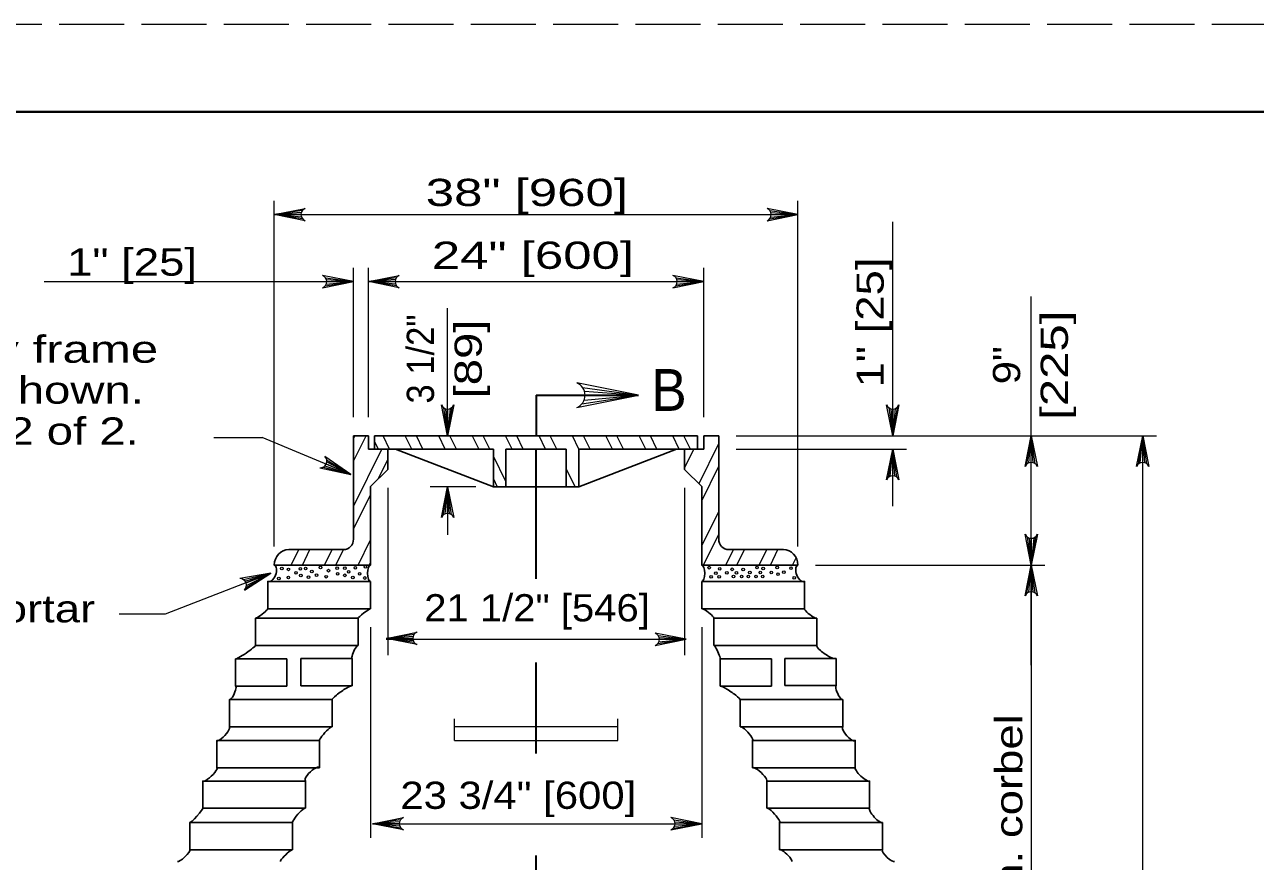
# Model space of a CAD drawing. Extents: x 1083.1 to 1117.1, y 697.4 to 741.4.
# Drawn here: x 1087.29 to 1094.35, y 736.56 to 741.35 of the extents above; entities that cross this region are included whole.
import ezdxf
from ezdxf.enums import TextEntityAlignment as Align

# ---------------------------------------------------------------- set-up
doc = ezdxf.new("R2010")
doc.units = 0
doc.header["$LTSCALE"] = 0.062
doc.linetypes.add('LONG_DASHED', pattern=[7.5, 6, -1.5])
doc.layers.add('1', color=7, linetype='Continuous', lineweight=13)

msp = doc.modelspace()

# ---------------------------------------------------------------- linework, layer by layer
at = {"layer": '1', "lineweight": 25}
for p, q in [((1085.12642, 740.85408), (1116.62642, 740.85408)), ((1089.17683, 738.40442), (1089.17683, 738.99733)), ((1089.17683, 738.99733), (1089.26217, 738.99733)), ((1089.26217, 738.92125), (1089.26217, 738.99733)), ((1089.29817, 738.92125), (1089.29817, 738.99733)), ((1089.29817, 738.99733), (1091.14983, 738.99733)), ((1091.14983, 738.92125), (1091.14983, 738.99733)), ((1091.18575, 738.92125), (1091.18575, 738.99733)), ((1091.27108, 738.99733), (1091.18575, 738.99733)), ((1091.27108, 738.40442), (1091.27108, 738.99733)), ((1089.26217, 738.92125), (1089.979, 738.92125)), ((1089.37358, 738.8045), (1089.37358, 738.92125)), ((1089.979, 738.70492), (1089.41875, 738.92125)), ((1089.979, 738.70492), (1089.979, 738.92125)), ((1090.05092, 738.70442), (1090.05083, 738.92125)), ((1090.05083, 738.92125), (1090.39708, 738.92125)), ((1090.39708, 738.70442), (1090.39708, 738.92125)), ((1090.469, 738.70492), (1090.46892, 738.92125)), ((1090.46892, 738.92125), (1091.18575, 738.92125)), ((1090.469, 738.70492), (1091.02917, 738.92125)), ((1091.07433, 738.8045), (1091.07433, 738.92125)), ((1089.27425, 738.70733), (1089.37358, 738.8045)), ((1091.17375, 738.70733), (1091.07433, 738.8045)), ((1089.979, 738.70492), (1090.05092, 738.70442)), ((1090.39708, 738.70442), (1090.05092, 738.70442)), ((1090.469, 738.70492), (1090.39708, 738.70442)), ((1088.80608, 738.34442), (1089.12025, 738.34442)), ((1091.64192, 738.34442), (1091.32775, 738.34442)), ((1089.27425, 738.00592), (1089.27425, 738.16192)), ((1091.17375, 738.00592), (1091.17375, 738.16192)), ((1088.685, 738.00592), (1089.27425, 738.00592)), ((1091.763, 738.00592), (1091.17375, 738.00592)), ((1089.20425, 737.79567), (1089.20425, 737.95158)), ((1091.24375, 737.79567), (1091.24375, 737.95158)), ((1088.615, 737.79567), (1089.20425, 737.79567)), ((1091.83292, 737.79567), (1091.24375, 737.79567)), ((1088.79558, 737.71808), (1088.50092, 737.71808)), ((1088.50092, 737.56217), (1088.50092, 737.71808)), ((1088.79558, 737.56217), (1088.79558, 737.71808)), ((1089.16958, 737.72033), (1088.875, 737.72033)), ((1088.875, 737.56442), (1088.875, 737.72033)), ((1089.16958, 737.56442), (1089.16958, 737.72033)), ((1091.57383, 737.71825), (1091.27925, 737.71825)), ((1091.27925, 737.56233), (1091.27925, 737.71825)), ((1091.57383, 737.56233), (1091.57383, 737.71825)), ((1091.94467, 737.72083), (1091.65, 737.72083)), ((1091.65, 737.56483), (1091.65, 737.72083)), ((1091.94467, 737.56483), (1091.94467, 737.72083)), ((1088.79558, 737.56217), (1088.50092, 737.56217)), ((1089.16958, 737.56442), (1088.875, 737.56442)), ((1091.57383, 737.56233), (1091.27925, 737.56233)), ((1091.94467, 737.56492), (1091.65, 737.56492)), ((1089.05475, 737.329), (1089.05475, 737.48492)), ((1091.39317, 737.329), (1091.39317, 737.48492)), ((1088.46558, 737.329), (1089.05475, 737.329)), ((1091.98242, 737.329), (1091.39317, 737.329)), ((1088.98292, 737.09467), (1088.98292, 737.25058)), ((1091.46508, 737.09467), (1091.46508, 737.25058)), ((1088.39367, 737.09467), (1088.98292, 737.09467)), ((1092.05433, 737.09467), (1091.46508, 737.09467)), ((1088.9015, 736.86233), (1088.9015, 737.01825)), ((1091.54642, 736.86233), (1091.54642, 737.01825)), ((1088.31233, 736.86233), (1088.9015, 736.86233)), ((1092.13567, 736.86233), (1091.54642, 736.86233)), ((1088.82775, 736.62392), (1088.82775, 736.77992)), ((1091.62017, 736.62392), (1091.62017, 736.77992)), ((1088.2385, 736.62392), (1088.82775, 736.62392)), ((1092.20942, 736.62392), (1091.62017, 736.62392))]:
    msp.add_line(p, q, dxfattribs=at)
at = {"layer": '1'}
for p, q in [((1088.72283, 738.36233), (1088.72283, 740.344)), ((1091.72517, 738.36233), (1091.72517, 740.344)), ((1088.88308, 740.28775), (1088.72283, 740.26533)), ((1088.87767, 740.27667), (1088.72283, 740.26533)), ((1088.72283, 740.26533), (1090.54142, 740.26533)), ((1088.876, 740.26533), (1088.72283, 740.26533)), ((1088.87883, 740.25092), (1088.72283, 740.26533)), ((1088.88492, 740.24058), (1088.72283, 740.26533)), ((1090.54142, 740.26533), (1091.72517, 740.26533)), ((1091.563, 740.24058), (1091.72517, 740.26533)), ((1091.56492, 740.28775), (1091.72517, 740.26533)), ((1091.56917, 740.25092), (1091.72517, 740.26533)), ((1091.57033, 740.27667), (1091.72517, 740.26533)), ((1091.572, 740.26533), (1091.72517, 740.26533)), ((1092.26917, 738.99733), (1092.26917, 740.22292)), ((1089.01658, 739.90325), (1089.17683, 739.88083)), ((1089.17683, 739.10342), (1089.17683, 739.9595)), ((1089.26217, 739.10342), (1089.26217, 739.9595)), ((1089.42242, 739.90325), (1089.26217, 739.88083)), ((1091.0255, 739.90325), (1091.18575, 739.88083)), ((1091.18575, 739.10342), (1091.18575, 739.9595)), ((1087.40358, 739.88083), (1089.17683, 739.88083)), ((1089.01475, 739.856), (1089.17683, 739.88083)), ((1089.02083, 739.86642), (1089.17683, 739.88083)), ((1089.02208, 739.89217), (1089.17683, 739.88083)), ((1089.02367, 739.88083), (1089.17683, 739.88083)), ((1089.417, 739.89217), (1089.26217, 739.88083)), ((1089.41533, 739.88083), (1089.26217, 739.88083)), ((1089.41817, 739.86642), (1089.26217, 739.88083)), ((1089.42433, 739.856), (1089.26217, 739.88083)), ((1089.26217, 739.88083), (1091.18575, 739.88083)), ((1091.02358, 739.856), (1091.18575, 739.88083)), ((1091.02975, 739.86642), (1091.18575, 739.88083)), ((1091.03092, 739.89217), (1091.18575, 739.88083)), ((1091.03258, 739.88083), (1091.18575, 739.88083)), ((1093.06292, 738.25633), (1093.06292, 739.79558)), ((1089.71608, 738.99733), (1089.71608, 739.72883)), ((1090.49083, 739.27442), (1090.81125, 739.22958)), ((1090.487, 739.18), (1090.81125, 739.22958)), ((1090.49933, 739.20075), (1090.81125, 739.22958)), ((1090.50167, 739.25225), (1090.81125, 739.22958)), ((1090.505, 739.22958), (1090.81125, 739.22958)), ((1089.69367, 739.15758), (1089.71608, 738.99733)), ((1089.70475, 739.15217), (1089.71608, 738.99733)), ((1089.74092, 739.1595), (1089.71608, 738.99733)), ((1089.7305, 739.15333), (1089.71608, 738.99733)), ((1089.71608, 739.1505), (1089.71608, 738.99733)), ((1092.24675, 739.15758), (1092.26917, 738.99733)), ((1092.25783, 739.15217), (1092.26917, 738.99733)), ((1092.29392, 739.1595), (1092.26917, 738.99733)), ((1092.2835, 739.15333), (1092.26917, 738.99733)), ((1092.26917, 739.1505), (1092.26917, 738.99733)), ((1088.3755, 738.9875), (1088.653, 738.9875)), ((1089.16083, 738.775), (1088.653, 738.9875)), ((1089.17683, 738.85092), (1089.249, 738.99733)), ((1089.17683, 738.98058), (1089.18517, 738.99733)), ((1089.38375, 738.92125), (1089.34625, 738.99733)), ((1089.39833, 738.99733), (1089.81625, 738.99733)), ((1089.5115, 738.92125), (1089.474, 738.99733)), ((1089.57542, 738.92125), (1089.53792, 738.99733)), ((1089.70317, 738.92125), (1089.66567, 738.99733)), ((1089.76708, 738.92125), (1089.72958, 738.99733)), ((1089.85733, 738.99733), (1089.89483, 738.92125)), ((1089.95875, 738.92125), (1089.92125, 738.99733)), ((1090.0865, 738.92125), (1090.049, 738.99733)), ((1090.15042, 738.92125), (1090.11292, 738.99733)), ((1090.27817, 738.92125), (1090.24067, 738.99733)), ((1090.34208, 738.92125), (1090.3045, 738.99733)), ((1090.46983, 738.92125), (1090.43233, 738.99733)), ((1090.53367, 738.92125), (1090.49617, 738.99733)), ((1090.6615, 738.92125), (1090.624, 738.99733)), ((1090.72533, 738.92125), (1090.68783, 738.99733)), ((1090.85317, 738.92125), (1090.81558, 738.99733)), ((1090.917, 738.92125), (1090.8795, 738.99733)), ((1091.04475, 738.92125), (1091.00725, 738.99733)), ((1091.10867, 738.92125), (1091.07117, 738.99733)), ((1091.37125, 738.99733), (1093.78125, 738.99733)), ((1091.37125, 738.99733), (1092.36925, 738.99733)), ((1091.47142, 738.99733), (1093.064, 738.99733)), ((1093.03817, 738.83525), (1093.06292, 738.99733)), ((1093.0485, 738.84133), (1093.06292, 738.99733)), ((1093.06292, 738.84417), (1093.06292, 738.99733)), ((1093.07425, 738.84258), (1093.06292, 738.99733)), ((1093.08533, 738.83708), (1093.06292, 738.99733)), ((1093.67775, 738.83525), (1093.70258, 738.99733)), ((1093.68817, 738.84133), (1093.70258, 738.99733)), ((1093.70258, 733.89467), (1093.70258, 738.99733)), ((1093.70258, 738.84417), (1093.70258, 738.99733)), ((1093.71392, 738.84258), (1093.70258, 738.99733)), ((1093.725, 738.83708), (1093.70258, 738.99733)), ((1089.17683, 738.59167), (1089.33925, 738.92125)), ((1089.31992, 738.92125), (1089.29817, 738.96533)), ((1091.07433, 738.81225), (1091.12808, 738.92125)), ((1091.158, 738.72275), (1091.27108, 738.95217)), ((1091.37125, 738.92125), (1092.34783, 738.92125)), ((1092.24433, 738.75908), (1092.26917, 738.92125)), ((1092.25475, 738.76525), (1092.26917, 738.92125)), ((1092.26917, 738.59308), (1092.26917, 738.92125)), ((1092.26917, 738.76808), (1092.26917, 738.92125)), ((1092.2805, 738.76642), (1092.26917, 738.92125)), ((1092.29158, 738.761), (1092.26917, 738.92125)), ((1089.02317, 738.86), (1089.16083, 738.775)), ((1089.02367, 738.84767), (1089.16083, 738.775)), ((1089.31958, 738.75167), (1089.37358, 738.86125)), ((1090.05092, 738.73425), (1089.979, 738.88017)), ((1089.00242, 738.81758), (1089.16083, 738.775)), ((1089.01225, 738.82458), (1089.16083, 738.775)), ((1089.02058, 738.83667), (1089.16083, 738.775)), ((1090.44875, 738.70483), (1090.39708, 738.80958)), ((1091.17375, 738.625), (1091.27108, 738.82258)), ((1089.37358, 738.69842), (1089.37358, 737.74058)), ((1089.87883, 738.70492), (1089.61592, 738.70492)), ((1089.69133, 738.54283), (1089.71608, 738.70492)), ((1089.70175, 738.54892), (1089.71608, 738.70492)), ((1089.71608, 738.70492), (1089.71608, 738.42975)), ((1089.71608, 738.55175), (1089.71608, 738.70492)), ((1089.72742, 738.55008), (1089.71608, 738.70492)), ((1089.7385, 738.54467), (1089.71608, 738.70492)), ((1089.979, 738.7505), (1090.0015, 738.70475)), ((1091.07433, 738.69842), (1091.07433, 737.74058)), ((1089.17683, 738.462), (1089.27425, 738.65958)), ((1091.17375, 738.36567), (1091.27108, 738.56325)), ((1091.18367, 738.25633), (1091.27108, 738.43367)), ((1093.0405, 738.41658), (1093.06292, 738.25633)), ((1093.08775, 738.41842), (1093.06292, 738.25633)), ((1088.81992, 738.25633), (1088.86333, 738.34442)), ((1088.88383, 738.25633), (1088.92725, 738.34442)), ((1089.01158, 738.25633), (1089.055, 738.34442)), ((1089.0755, 738.25633), (1089.11892, 738.34442)), ((1089.20325, 738.25633), (1089.27425, 738.40033)), ((1091.3115, 738.25633), (1091.35492, 738.34442)), ((1091.37533, 738.25633), (1091.41875, 738.34442)), ((1091.50308, 738.25633), (1091.54658, 738.34442)), ((1091.567, 738.25633), (1091.61042, 738.34442)), ((1093.05158, 738.41108), (1093.06292, 738.25633)), ((1093.07733, 738.41233), (1093.06292, 738.25633)), ((1093.06292, 738.4095), (1093.06292, 738.25633)), ((1091.69475, 738.25633), (1091.71525, 738.29792)), ((1088.54625, 738.17258), (1088.70392, 738.20908)), ((1088.55533, 738.16417), (1088.70392, 738.20908)), ((1088.56092, 738.15417), (1088.70392, 738.20908)), ((1088.56142, 738.12783), (1088.70392, 738.20908)), ((1088.56342, 738.13975), (1088.70392, 738.20908)), ((1089.26717, 738.25633), (1089.27425, 738.27067)), ((1091.82525, 738.25633), (1093.14158, 738.25633)), ((1093.03817, 738.09417), (1093.06292, 738.25633)), ((1093.0485, 738.10033), (1093.06292, 738.25633)), ((1093.06292, 738.25633), (1093.06292, 735.13425)), ((1093.06292, 737.68233), (1093.06292, 738.25633)), ((1093.06292, 738.10317), (1093.06292, 738.25633)), ((1093.07425, 738.1015), (1093.06292, 738.25633)), ((1093.08533, 738.09608), (1093.06292, 738.25633)), ((1089.27425, 737.89992), (1089.27425, 736.692)), ((1089.52442, 737.8585), (1089.36417, 737.83608)), ((1090.92358, 737.85292), (1091.08383, 737.8305)), ((1091.17375, 737.89992), (1091.17375, 736.692)), ((1089.519, 737.84742), (1089.36417, 737.83608)), ((1089.51733, 737.83608), (1089.36417, 737.83608)), ((1089.52017, 737.82167), (1089.36417, 737.83608)), ((1089.52625, 737.81133), (1089.36417, 737.83608)), ((1089.36417, 737.8305), (1091.07433, 737.8305)), ((1090.92167, 737.80567), (1091.08383, 737.8305)), ((1090.92783, 737.81608), (1091.08383, 737.8305)), ((1090.929, 737.84183), (1091.08383, 737.8305)), ((1090.93067, 737.8305), (1091.08383, 737.8305)), ((1089.75575, 737.25), (1089.75575, 737.37533)), ((1090.69217, 737.25), (1090.69217, 737.37533)), ((1089.75575, 737.33133), (1090.69217, 737.33133)), ((1089.75575, 737.25), (1090.69217, 737.25)), ((1089.44642, 736.79592), (1089.28625, 736.77342)), ((1091.0135, 736.79592), (1091.17375, 736.77342)), ((1089.441, 736.78475), (1089.28625, 736.77342)), ((1089.43942, 736.77342), (1089.28625, 736.77342)), ((1089.44225, 736.75908), (1089.28625, 736.77342)), ((1089.44833, 736.74867), (1089.28625, 736.77342)), ((1089.28625, 736.77342), (1091.17375, 736.77342)), ((1091.01158, 736.74867), (1091.17375, 736.77342)), ((1091.01775, 736.75908), (1091.17375, 736.77342)), ((1091.01892, 736.78475), (1091.17375, 736.77342)), ((1091.02058, 736.77342), (1091.17375, 736.77342))]:
    msp.add_line(p, q, dxfattribs=at)
at = {"layer": '1', "lineweight": 35}
for p, q in [((1090.224, 739.22958), (1090.81125, 739.22958)), ((1090.224, 739.22958), (1090.224, 738.99733)), ((1090.224, 738.17692), (1090.224, 738.92125)), ((1090.224, 737.1755), (1090.224, 737.69717)), ((1090.224, 730.90125), (1090.224, 736.59083))]:
    msp.add_line(p, q, dxfattribs=at)
at = {"layer": '1', "linetype": 'LONG_DASHED'}
msp.add_lwpolyline([(1083.12642, 719.35408), (1117.12642, 719.35408), (1117.12642, 741.35408), (1083.12642, 741.35408)], close=True, dxfattribs=at)
at = {"layer": '1', "lineweight": 40}
msp.add_lwpolyline([(1085.12642, 740.85408), (1116.62642, 740.85408), (1116.62642, 719.85408), (1085.12642, 719.85408)], close=True, dxfattribs=at)
at = {"layer": '1'}
for points in [[(1088.89983, 740.22992), (1088.72283, 740.26533), (1088.89983, 740.30075)], [(1091.54817, 740.22992), (1091.72517, 740.26533), (1091.54817, 740.30075)], [(1088.99983, 739.84542), (1089.17683, 739.88083), (1088.99983, 739.91625)], [(1089.43917, 739.84542), (1089.26217, 739.88083), (1089.43917, 739.91625)], [(1091.00875, 739.84542), (1091.18575, 739.88083), (1091.00875, 739.91625)], [(1089.26217, 739.88083), (1090.52358, 739.88083), (1091.18575, 739.88083)], [(1090.45725, 739.15875), (1090.81125, 739.22958), (1090.45725, 739.30033)], [(1089.7515, 739.17433), (1089.71608, 738.99733), (1089.68067, 739.17433)], [(1092.3045, 739.17433), (1092.26917, 738.99733), (1092.23375, 739.17433)], [(1093.0275, 738.82033), (1093.06292, 738.99733), (1093.09833, 738.82033)], [(1093.66717, 738.82033), (1093.70258, 738.99733), (1093.738, 738.82033)], [(1092.23375, 738.74425), (1092.26917, 738.92125), (1092.3045, 738.74425)], [(1088.9845, 738.81383), (1089.16083, 738.775), (1089.01308, 738.87867)], [(1089.68067, 738.52792), (1089.71608, 738.70492), (1089.7515, 738.52792)], [(1093.09833, 738.43333), (1093.06292, 738.25633), (1093.0275, 738.43333)], [(1088.70392, 738.20908), (1088.09783, 737.97517), (1087.83292, 737.97517)], [(1088.55133, 738.11258), (1088.70392, 738.20908), (1088.526, 738.17875)], [(1093.0275, 738.07933), (1093.06292, 738.25633), (1093.09833, 738.07933)], [(1089.54117, 737.80067), (1089.36417, 737.83608), (1089.54117, 737.8715)], [(1090.90683, 737.79508), (1091.08383, 737.8305), (1090.90683, 737.86592)], [(1089.46325, 736.73808), (1089.28625, 736.77342), (1089.46325, 736.80883)], [(1090.99675, 736.73808), (1091.17375, 736.77342), (1090.99675, 736.80883)]]:
    msp.add_lwpolyline(points, dxfattribs=at)
at = {"layer": '1', "lineweight": 25}
for points in [[(1088.72283, 738.25633), (1089.27425, 738.25633), (1089.27425, 738.70733)], [(1091.72517, 738.25633), (1091.17375, 738.25633), (1091.17375, 738.70733)], [(1088.685, 738.00592), (1088.685, 738.16192), (1089.27425, 738.16192)], [(1091.763, 738.00592), (1091.763, 738.16192), (1091.17375, 738.16192)], [(1088.615, 737.79567), (1088.615, 737.95158), (1089.20425, 737.95158)], [(1091.83292, 737.79567), (1091.83292, 737.95158), (1091.24375, 737.95158)], [(1088.46558, 737.329), (1088.46558, 737.48492), (1089.05475, 737.48492)], [(1091.98242, 737.329), (1091.98242, 737.48492), (1091.39317, 737.48492)], [(1088.39367, 737.09467), (1088.39367, 737.25058), (1088.98292, 737.25058)], [(1092.05433, 737.09467), (1092.05433, 737.25058), (1091.46508, 737.25058)], [(1088.31233, 736.86233), (1088.31233, 737.01825), (1088.9015, 737.01825)], [(1092.13567, 736.86233), (1092.13567, 737.01825), (1091.54642, 737.01825)], [(1088.2385, 736.62392), (1088.2385, 736.77992), (1088.82775, 736.77992)], [(1092.20942, 736.62392), (1092.20942, 736.77992), (1091.62017, 736.77992)]]:
    msp.add_lwpolyline(points, dxfattribs=at)
at = {"layer": '1'}
for centre, radius, start, end in [((1088.91411, 740.26539), 0.0382, 112.08782, 247.91395), ((1091.53383, 740.26539), 0.0382, 292.08605, 67.91218), ((1088.98556, 739.88085), 0.0382, 292.08605, 67.91218), ((1089.4535, 739.88085), 0.0382, 112.08782, 247.91395), ((1090.99445, 739.88085), 0.0382, 292.08605, 67.91218), ((1090.4287, 739.22964), 0.0764, 292.08605, 67.91218), ((1089.71607, 739.18866), 0.0382, 202.08782, 337.91395), ((1092.26909, 739.18866), 0.0382, 202.08782, 337.91395), ((1088.98573, 738.85203), 0.0382, 268.33738, 44.16351), ((1093.06298, 738.80607), 0.0382, 22.08782, 157.91395), ((1093.7026, 738.80607), 0.0382, 22.08782, 157.91395), ((1092.26917, 738.72996), 0.0382, 22.08782, 157.91395), ((1089.71615, 738.51364), 0.0382, 22.08782, 157.91395), ((1093.0629, 738.44759), 0.0382, 202.08782, 337.91395), ((1088.52531, 738.14058), 0.0382, 313.08668, 88.9128), ((1093.06298, 738.065), 0.0382, 22.08782, 157.91395), ((1089.55545, 737.83614), 0.0382, 112.08782, 247.91395), ((1090.8925, 737.83052), 0.0382, 292.08605, 67.91218), ((1089.47751, 736.77349), 0.0382, 112.08782, 247.91395), ((1090.98243, 736.77349), 0.0382, 292.08605, 67.91218)]:
    msp.add_arc(centre, radius, start, end, dxfattribs=at)
at = {"layer": '1', "lineweight": 25}
for centre, major_axis, ratio, start_param, end_param in [((1088.80606, 738.2563), (0, 0.08813), 0.944544, 0.0000048, 1.5708011), ((1089.12022, 738.40439), (0, -0.05997), 0.944544, 0.000001, 1.5707952), ((1091.32773, 738.40439), (0, 0.05997), 0.944544, 1.5707952, 3.1415937), ((1091.64189, 738.2563), (0, 0.08813), 0.944544, 4.7123842, 6.2831805), ((1088.70391, 738.2091), (0.01807, 0.04755), 0.550574, 3.1091398, 6.2507324), ((1089.27423, 738.2091), (0, -0.0472), 0.356664, 3.1415929, 6.2831855), ((1091.17372, 738.2091), (0, -0.0472), 0.356664, 6.2831851, 9.4247777), ((1091.74404, 738.2091), (-0.01807, 0.04755), 0.550574, 0.0324529, 3.1740455), ((1088.64999, 737.97877), (0.03498, 0.0272), 0.123309, 3.1347753, 6.276368), ((1089.23923, 737.97877), (-0.03499, -0.02719), 0.095152, 3.1363648, 6.2779574), ((1091.20872, 737.97877), (0.03496, -0.02722), 0.153945, 0.0085851, 3.1501778), ((1091.79796, 737.97877), (-0.03495, 0.02724), 0.182617, 0.0102861, 3.1518788), ((1088.55797, 737.75688), (0.05701, 0.03878), 0.08505, 3.1371461, 6.2787387), ((1089.18691, 737.75799), (-0.01723, -0.03769), 0.223335, 3.131028, 6.2726207), ((1091.26147, 737.75696), (0.01773, -0.03869), 0.12471, 0.0056867, 3.1472794), ((1091.8888, 737.75823), (-0.05576, 0.03755), 0.215308, 0.0116463, 3.153239), ((1089.11219, 737.52466), (-0.05738, -0.03979), 0.123692, 3.1350238, 6.2766165), ((1088.48324, 737.52355), (0.01758, 0.03869), 0.261975, 3.1289792, 6.2705719), ((1091.3362, 737.52363), (0.05694, -0.03875), 0.114762, 0.0060354, 3.1476281), ((1091.96353, 737.5249), (-0.01874, 0.04005), 0.262161, 0.0128537, 3.1544464), ((1088.4296, 737.28978), (0.03579, 0.03934), 0.255117, 3.1260199, 6.2676126), ((1089.01883, 737.28978), (-0.03589, -0.03924), 0.153621, 3.1326147, 6.2742074), ((1091.42911, 737.28978), (0.03583, -0.0393), 0.2262, 0.0136046, 3.1551973), ((1092.01835, 737.28977), (-0.03567, 0.03945), 0.332158, 0.0213096, 3.1629023), ((1088.35298, 737.05644), (0.04053, 0.03834), 0.248819, 3.1265579, 6.2681506), ((1088.94222, 737.05644), (0.04038, 0.03851), 0.348106, 6.2607285, 9.4023212), ((1091.50573, 737.05644), (0.04056, -0.03832), 0.228756, 0.0136823, 3.155275), ((1092.09497, 737.05644), (-0.04055, 0.03833), 0.239953, 0.0144322, 3.1560248), ((1088.27542, 736.8211), (0.03686, 0.04122), 0.109562, 3.1352712, 6.2768638), ((1088.86465, 736.8211), (-0.03683, -0.04125), 0.157731, 3.1323715, 6.2739642), ((1091.5833, 736.8211), (0.03679, -0.04129), 0.204334, 0.0121564, 3.1537491), ((1092.17253, 736.8211), (-0.03675, 0.04132), 0.238818, 0.0144388, 3.1560314), ((1088.20353, 736.59077), (0.03491, 0.03328), 0.214158, 3.1288563, 6.2704489), ((1088.79276, 736.59077), (-0.03496, -0.03322), 0.136714, 3.1336877, 6.2752804), ((1091.65519, 736.59077), (0.0349, -0.03329), 0.223095, 0.0133225, 3.1549152), ((1092.24442, 736.59077), (-0.03485, 0.03334), 0.271388, 0.0166254, 3.158218)]:
    msp.add_ellipse(centre, major_axis=major_axis, ratio=ratio, start_param=start_param, end_param=end_param, dxfattribs=at)
at = {"layer": '1'}
for centre in [(1088.76618, 738.23586), (1088.8038, 738.23151), (1088.84754, 738.21089), (1088.87235, 738.23395), (1088.87487, 738.1962), (1088.90253, 738.23664), (1088.93806, 738.21899), (1088.96535, 738.19849), (1088.98755, 738.24188), (1089.03405, 738.22415), (1089.08348, 738.23833), (1089.08603, 738.20638), (1089.1271, 738.1974), (1089.12734, 738.23803), (1089.14915, 738.21757), (1089.18767, 738.24053), (1089.21214, 738.20553), (1089.24528, 738.24594), (1091.21646, 738.24136), (1091.25465, 738.20918), (1091.27674, 738.23515), (1091.31772, 738.21165), (1091.348, 738.23176), (1091.37255, 738.21128), (1091.41106, 738.23134), (1091.44933, 738.21367), (1091.49063, 738.24241), (1091.50964, 738.21326), (1091.52623, 738.23637), (1091.5727, 738.21284), (1091.60577, 738.24164), (1091.61103, 738.20387), (1091.644, 738.21526), (1091.68526, 738.2382), (1088.74865, 738.17963), (1088.80352, 738.18507), (1088.91868, 738.18719), (1089.02013, 738.18941), (1089.17363, 738.18547), (1089.24216, 738.18211), (1091.22711, 738.18904), (1091.27372, 738.18873), (1091.35598, 738.19108), (1091.40259, 738.19076), (1091.44097, 738.1905), (1091.48483, 738.19021), (1091.52321, 738.18995), (1091.70412, 738.18292)]:
    msp.add_ellipse(centre, major_axis=(0, 0.00779), ratio=0.944544, dxfattribs=at)

# ---------------------------------------------------------------- texts
for s, height, width, p in [('38" [960]', 0.156, 1.4, (1089.5915, 740.31417)), ('24" [600]', 0.156, 1.4, (1089.62625, 739.95417)), ('1" [25]', 0.156, 1.25, (1087.535, 739.915)), ('Heavy duty frame', 0.156, 1.35, (1085.85, 739.41583)), ('and cover shown.', 0.156, 1.3, (1085.85, 739.18117)), ('B', 0.24, 0.95, (1090.88417, 739.13983)), ('See Sheet 2 of 2.', 0.156, 1.3, (1085.85, 738.9465)), ('Mortar', 0.156, 1.25, (1086.94292, 737.92783)), ('23 3/4" [600]', 0.156, 1.15, (1089.44575, 736.85858))]:
    msp.add_text(s, height=height, dxfattribs=dict(at, width=width)).set_placement(p)
at = {"layer": '1', "width": 1.25}
for s, p in [('1" [25]', (1092.21708, 739.27408)), ('4\'-0" [1.2 m] min. corbel', (1093.01158, 734.66483))]:
    msp.add_text(s, height=0.156, rotation=90, dxfattribs=at).set_placement(p)
at = {"layer": '1'}
for s, width, p in [('3 1/2"', 0.95, (1089.6385, 739.43746)), ('[225]', 1.35, (1093.27325, 739.40158)), ('[89]', 1.3, (1089.9125, 739.43754)), ('9"', 1.15, (1092.99925, 739.40158))]:
    msp.add_text(s, height=0.156, rotation=90, dxfattribs=dict(at, width=width)).set_placement(p, align=Align.CENTER)
at = {"layer": '1', "width": 1.1}
msp.add_text('21 1/2" [546]', height=0.156, dxfattribs=at).set_placement((1090.22933, 737.93325), align=Align.CENTER)

doc.saveas('drawing.dxf')
